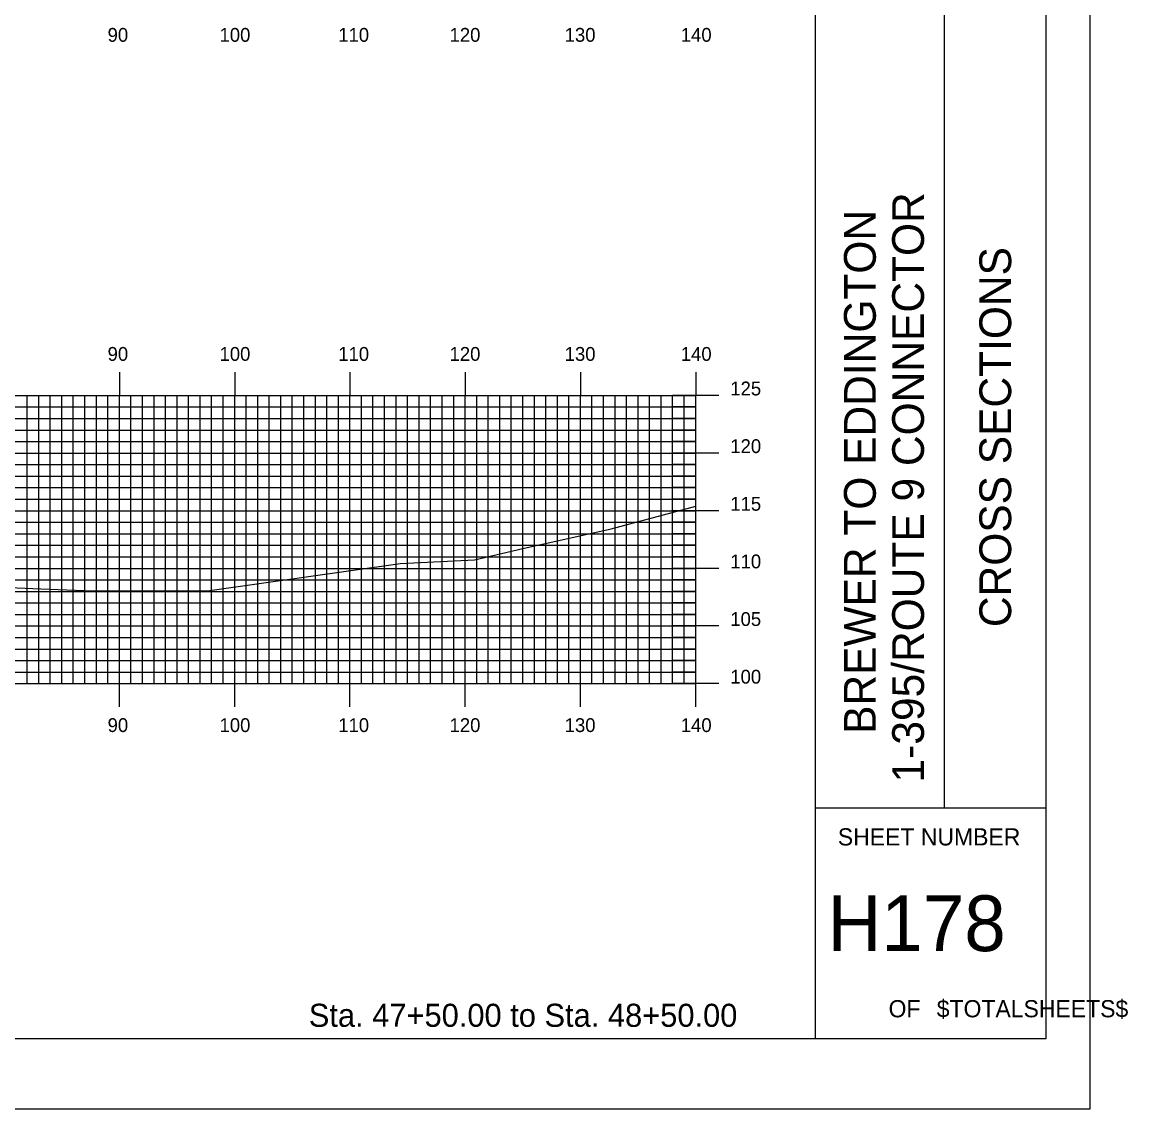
# Model space of a CAD drawing. Extents: x 1754708 to 1755051, y 442591 to 442811.
# Drawn here: x 1754955.1 to 1755051, y 442590.5 to 442684.8 of the extents above; entities that cross this region are included whole.
import ezdxf

# ---------------------------------------------------------------- set-up
doc = ezdxf.new("R2010")
doc.units = 0
for name, color, linetype in [('BORDER', 7, 'Continuous'), ('H_V ANNOTATION', 7, 'Continuous'), ('MAJOR', 7, 'Continuous'), ('MINOR', 7, 'Continuous'), ('PLOT BOUNDARY', 7, 'Continuous'), ('S_Roadway_Centerline', 7, 'Continuous')]:
    doc.layers.add(name, color=color, linetype=linetype)

msp = doc.modelspace()

# ---------------------------------------------------------------- linework, layer by layer
at = {"layer": 'BORDER'}
for p, q in [((1755023.917, 442596.665), (1755023.917, 442806.665)), ((1755035.099, 442616.671), (1755035.099, 442686.671)), ((1755023.917, 442616.671), (1755043.917, 442616.671))]:
    msp.add_line(p, q, dxfattribs=at)
msp.add_lwpolyline([(1754723.917, 442596.665), (1755043.917, 442596.665), (1755043.917, 442806.665), (1754723.917, 442806.665)], close=True, dxfattribs=at)
at = {"layer": 'MAJOR'}
for p, q in [((1754963.517, 442654.44), (1754963.517, 442652.436)), ((1754973.517, 442654.44), (1754973.517, 442652.436)), ((1754983.517, 442654.44), (1754983.517, 442652.436)), ((1754993.517, 442654.44), (1754993.517, 442652.436)), ((1755003.517, 442654.44), (1755003.517, 442652.436)), ((1755013.517, 442654.44), (1755013.517, 442652.436)), ((1754733.517, 442652.436), (1755013.517, 442652.436)), ((1754733.517, 442652.436), (1755013.517, 442652.436)), ((1754963.517, 442627.436), (1754963.517, 442652.436)), ((1754973.517, 442627.436), (1754973.517, 442652.436)), ((1754983.517, 442627.436), (1754983.517, 442652.436)), ((1754993.517, 442627.436), (1754993.517, 442652.436)), ((1755003.517, 442627.436), (1755003.517, 442652.436)), ((1755015.521, 442652.436), (1755011.513, 442652.436)), ((1755013.517, 442627.436), (1755013.517, 442652.436)), ((1755013.517, 442627.436), (1755013.517, 442652.436)), ((1754733.517, 442647.436), (1755013.517, 442647.436)), ((1755015.521, 442647.436), (1755011.513, 442647.436)), ((1754733.517, 442642.436), (1755013.517, 442642.436)), ((1755015.521, 442642.436), (1755011.513, 442642.436)), ((1754733.517, 442637.436), (1755013.517, 442637.436)), ((1755015.521, 442637.436), (1755011.513, 442637.436)), ((1754733.517, 442632.436), (1755013.517, 442632.436)), ((1755015.521, 442632.436), (1755011.513, 442632.436)), ((1754733.517, 442627.436), (1755013.517, 442627.436)), ((1754733.517, 442627.436), (1755013.517, 442627.436)), ((1754963.517, 442625.432), (1754963.517, 442627.436)), ((1754973.517, 442625.432), (1754973.517, 442627.436)), ((1754983.517, 442625.432), (1754983.517, 442627.436)), ((1754993.517, 442625.432), (1754993.517, 442627.436)), ((1755003.517, 442625.432), (1755003.517, 442627.436)), ((1755015.521, 442627.436), (1755011.513, 442627.436)), ((1755013.517, 442625.432), (1755013.517, 442627.436))]:
    msp.add_line(p, q, dxfattribs=at)
at = {"layer": 'MINOR'}
for p, q in [((1754955.517, 442627.436), (1754955.517, 442652.436)), ((1754956.517, 442627.436), (1754956.517, 442652.436)), ((1754957.517, 442627.436), (1754957.517, 442652.436)), ((1754958.517, 442627.436), (1754958.517, 442652.436)), ((1754959.517, 442627.436), (1754959.517, 442652.436)), ((1754960.517, 442627.436), (1754960.517, 442652.436)), ((1754961.517, 442627.436), (1754961.517, 442652.436)), ((1754962.517, 442627.436), (1754962.517, 442652.436)), ((1754964.517, 442627.436), (1754964.517, 442652.436)), ((1754965.517, 442627.436), (1754965.517, 442652.436)), ((1754966.517, 442627.436), (1754966.517, 442652.436)), ((1754967.517, 442627.436), (1754967.517, 442652.436)), ((1754968.517, 442627.436), (1754968.517, 442652.436)), ((1754969.517, 442627.436), (1754969.517, 442652.436)), ((1754970.517, 442627.436), (1754970.517, 442652.436)), ((1754971.517, 442627.436), (1754971.517, 442652.436)), ((1754972.517, 442627.436), (1754972.517, 442652.436)), ((1754974.517, 442627.436), (1754974.517, 442652.436)), ((1754975.517, 442627.436), (1754975.517, 442652.436)), ((1754976.517, 442627.436), (1754976.517, 442652.436)), ((1754977.517, 442627.436), (1754977.517, 442652.436)), ((1754978.517, 442627.436), (1754978.517, 442652.436)), ((1754979.517, 442627.436), (1754979.517, 442652.436)), ((1754980.517, 442627.436), (1754980.517, 442652.436)), ((1754981.517, 442627.436), (1754981.517, 442652.436)), ((1754982.517, 442627.436), (1754982.517, 442652.436)), ((1754984.517, 442627.436), (1754984.517, 442652.436)), ((1754985.517, 442627.436), (1754985.517, 442652.436)), ((1754986.517, 442627.436), (1754986.517, 442652.436)), ((1754987.517, 442627.436), (1754987.517, 442652.436)), ((1754988.517, 442627.436), (1754988.517, 442652.436)), ((1754989.517, 442627.436), (1754989.517, 442652.436)), ((1754990.517, 442627.436), (1754990.517, 442652.436)), ((1754991.517, 442627.436), (1754991.517, 442652.436)), ((1754992.517, 442627.436), (1754992.517, 442652.436)), ((1754994.517, 442627.436), (1754994.517, 442652.436)), ((1754995.517, 442627.436), (1754995.517, 442652.436)), ((1754996.517, 442627.436), (1754996.517, 442652.436)), ((1754997.517, 442627.436), (1754997.517, 442652.436)), ((1754998.517, 442627.436), (1754998.517, 442652.436)), ((1754999.517, 442627.436), (1754999.517, 442652.436)), ((1755000.517, 442627.436), (1755000.517, 442652.436)), ((1755001.517, 442627.436), (1755001.517, 442652.436)), ((1755002.517, 442627.436), (1755002.517, 442652.436)), ((1755004.517, 442627.436), (1755004.517, 442652.436)), ((1755005.517, 442627.436), (1755005.517, 442652.436)), ((1755006.517, 442627.436), (1755006.517, 442652.436)), ((1755007.517, 442627.436), (1755007.517, 442652.436)), ((1755008.517, 442627.436), (1755008.517, 442652.436)), ((1755009.517, 442627.436), (1755009.517, 442652.436)), ((1755010.517, 442627.436), (1755010.517, 442652.436)), ((1755011.517, 442627.436), (1755011.517, 442652.436)), ((1755012.517, 442627.436), (1755012.517, 442652.436)), ((1754733.517, 442651.436), (1755013.517, 442651.436)), ((1755013.517, 442651.436), (1755011.513, 442651.436)), ((1754733.517, 442650.436), (1755013.517, 442650.436)), ((1755013.517, 442650.436), (1755011.513, 442650.436)), ((1754733.517, 442649.436), (1755013.517, 442649.436)), ((1755013.517, 442649.436), (1755011.513, 442649.436)), ((1754733.517, 442648.436), (1755013.517, 442648.436)), ((1755013.517, 442648.436), (1755011.513, 442648.436)), ((1754733.517, 442646.436), (1755013.517, 442646.436)), ((1755013.517, 442646.436), (1755011.513, 442646.436)), ((1754733.517, 442645.436), (1755013.517, 442645.436)), ((1755013.517, 442645.436), (1755011.513, 442645.436)), ((1754733.517, 442644.436), (1755013.517, 442644.436)), ((1755013.517, 442644.436), (1755011.513, 442644.436)), ((1754733.517, 442643.436), (1755013.517, 442643.436)), ((1755013.517, 442643.436), (1755011.513, 442643.436)), ((1754733.517, 442641.436), (1755013.517, 442641.436)), ((1755013.517, 442641.436), (1755011.513, 442641.436)), ((1754733.517, 442640.436), (1755013.517, 442640.436)), ((1755013.517, 442640.436), (1755011.513, 442640.436)), ((1754733.517, 442639.436), (1755013.517, 442639.436)), ((1755013.517, 442639.436), (1755011.513, 442639.436)), ((1754733.517, 442638.436), (1755013.517, 442638.436)), ((1755013.517, 442638.436), (1755011.513, 442638.436)), ((1754733.517, 442636.436), (1755013.517, 442636.436)), ((1755013.517, 442636.436), (1755011.513, 442636.436)), ((1754733.517, 442635.436), (1755013.517, 442635.436)), ((1755013.517, 442635.436), (1755011.513, 442635.436)), ((1754733.517, 442634.436), (1755013.517, 442634.436)), ((1755013.517, 442634.436), (1755011.513, 442634.436)), ((1754733.517, 442633.436), (1755013.517, 442633.436)), ((1755013.517, 442633.436), (1755011.513, 442633.436)), ((1754733.517, 442631.436), (1755013.517, 442631.436)), ((1755013.517, 442631.436), (1755011.513, 442631.436)), ((1754733.517, 442630.436), (1755013.517, 442630.436)), ((1755013.517, 442630.436), (1755011.513, 442630.436)), ((1754733.517, 442629.436), (1755013.517, 442629.436)), ((1755013.517, 442629.436), (1755011.513, 442629.436)), ((1754733.517, 442628.436), (1755013.517, 442628.436)), ((1755013.517, 442628.436), (1755011.513, 442628.436))]:
    msp.add_line(p, q, dxfattribs=at)
at = {"layer": 'PLOT BOUNDARY'}
msp.add_lwpolyline([(1754707.731, 442590.547), (1755047.731, 442590.547), (1755047.731, 442810.547), (1754707.731, 442810.547)], close=True, dxfattribs=at)
at = {"layer": 'S_Roadway_Centerline'}
msp.add_lwpolyline([(1754947.765, 442636.036), (1754956.702, 442635.659), (1754961.213, 442635.483), (1754971.366, 442635.52), (1754987.889, 442637.87), (1754994.311, 442638.177), (1754998.525, 442639.145), (1755006.181, 442640.866), (1755013.517, 442642.817)], dxfattribs=at)

# ---------------------------------------------------------------- texts
at = {"layer": 'BORDER'}
for s, p in [('1-395/ROUTE 9 CONNECTOR', (1755033.32, 442618.865)), ('BREWER TO EDDINGTON', (1755029.14, 442623.074)), ('CROSS SECTIONS', (1755040.886, 442632.339))]:
    msp.add_text(s, height=2.75575, rotation=90, dxfattribs=at).set_placement(p)
for s, height, p in [('SHEET NUMBER', 1.49054, (1755025.848, 442613.398)), ('H178', 4.8388, (1755024.948, 442604.23)), ('OF', 1.4905, (1755030.251, 442598.491)), ('$TOTALSHEETS$', 1.49054, (1755034.43, 442598.491))]:
    msp.add_text(s, height=height, dxfattribs=at).set_placement(p)
at = {"layer": 'H_V ANNOTATION'}
for s, height, p in [('90', 1.2, (1754962.49, 442683.112)), ('100', 1.2, (1754972.201, 442683.112)), ('110', 1.2, (1754982.501, 442683.112)), ('120', 1.2, (1754992.158, 442683.112)), ('130', 1.2, (1755002.147, 442683.112)), ('140', 1.2, (1755012.222, 442683.112)), ('90', 1.2, (1754962.49, 442655.436)), ('100', 1.2, (1754972.201, 442655.436)), ('110', 1.2, (1754982.501, 442655.436)), ('120', 1.2, (1754992.158, 442655.436)), ('130', 1.2, (1755002.147, 442655.436)), ('140', 1.2, (1755012.222, 442655.436)), ('125', 1.2, (1755016.517, 442652.436)), ('120', 1.2, (1755016.517, 442647.436)), ('115', 1.2, (1755016.517, 442642.436)), ('110', 1.2, (1755016.517, 442637.436)), ('105', 1.2, (1755016.517, 442632.436)), ('100', 1.2, (1755016.517, 442627.436)), ('90', 1.2, (1754962.49, 442623.236)), ('100', 1.2, (1754972.201, 442623.236)), ('110', 1.2, (1754982.501, 442623.236)), ('120', 1.2, (1754992.158, 442623.236)), ('130', 1.2, (1755002.147, 442623.236)), ('140', 1.2, (1755012.222, 442623.236)), ('Sta. 47+50.00 to Sta. 48+50.00', 2.0004, (1754979.948, 442597.665))]:
    msp.add_text(s, height=height, dxfattribs=at).set_placement(p)

doc.saveas('drawing.dxf')
